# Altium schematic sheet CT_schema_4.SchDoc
size 368 x 245 mm
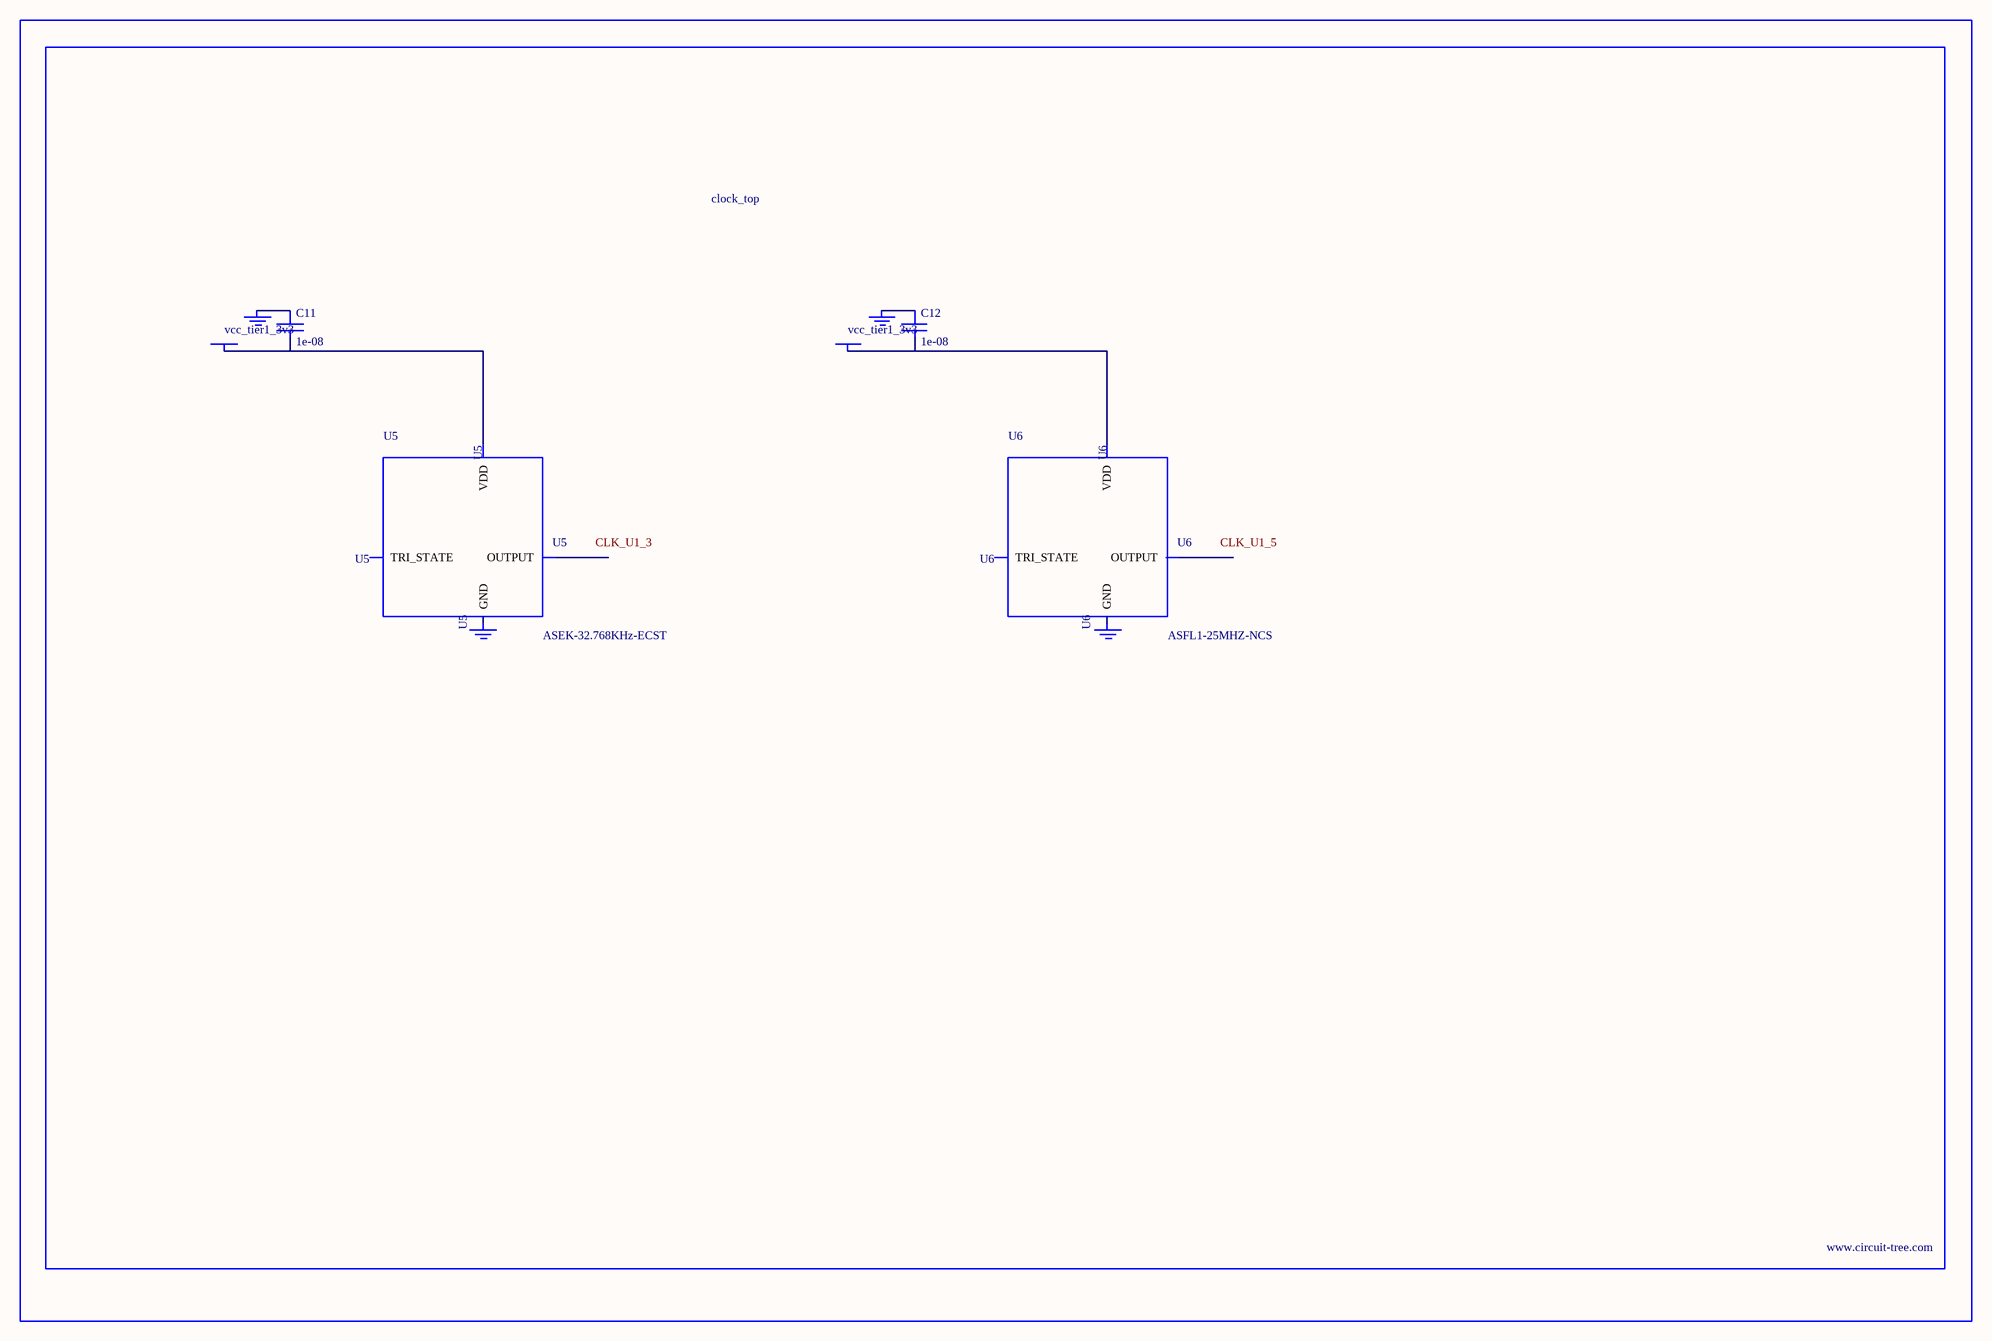
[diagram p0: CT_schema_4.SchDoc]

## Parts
BORDER3  (no value)
C11  1e-08  [C0402]
C12  1e-08  [C0402]
GND_INSTANCE_3_0  (no value)
GND_INSTANCE_3_1  (no value)
GND_INSTANCE_3_2  (no value)
GND_INSTANCE_3_3  (no value)
POWER_INSTANCE_3_0  vcc_tier1_3v3
POWER_INSTANCE_3_1  vcc_tier1_3v3
U5  ASEK-32.768KHz-ECST  [ASEK]
U6  ASFL1-25MHZ-NCS  [ASFL1]

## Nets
NetC11_1: C11.1 GND_INSTANCE_3_0.0(GND)
NetC11_2: C11.2 POWER_INSTANCE_3_0.0(PWR) U5.4(VDD)
NetC12_1: C12.1 GND_INSTANCE_3_2.0(GND)
NetC12_2: C12.2 POWER_INSTANCE_3_1.0(PWR) U6.4(VDD)

Not connected (* = marked no-connect by the designer): GND_INSTANCE_3_1 0(GND); GND_INSTANCE_3_3 0(GND); U5 1(TRI_STATE) 2(GND) 3(OUTPUT); U6 1(TRI_STATE) 2(GND) 3(OUTPUT)

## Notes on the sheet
- Labels drawn without touching a wire or pin: CLK_U1_3, CLK_U1_5

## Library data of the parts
BORDER3 = BORDER_PAGE3
C11 C12 = C0402C103K3RAC
GND_INSTANCE_3_0-GND_INSTANCE_3_3 = GND
POWER_INSTANCE_3_0 POWER_INSTANCE_3_1 = PWR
